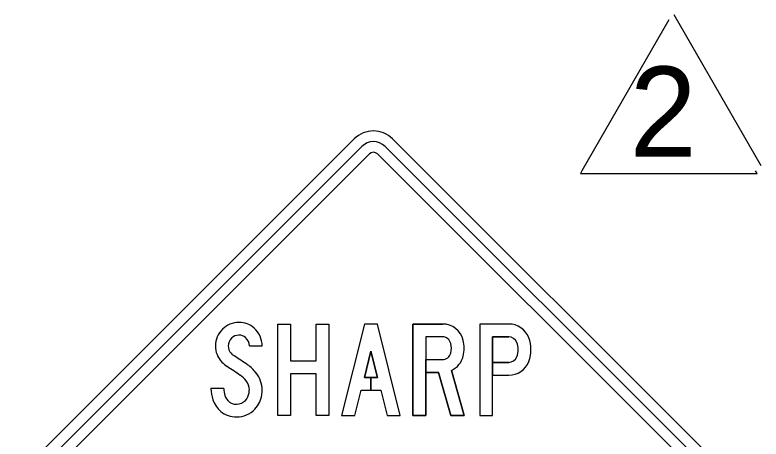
# Model space of a CAD drawing. Extents: x 2195 to 2411, y 202 to 481.
# Drawn here: x 2370.13 to 2382.1, y 351.9 to 358.71 of the extents above; entities that cross this region are included whole.
import ezdxf

# ---------------------------------------------------------------- set-up
doc = ezdxf.new("R2010")
doc.units = 0
for name, color, linetype in [('GSBWFILL', 7, 'Continuous'), ('GSCOLORFILL', 7, 'Continuous'), ('GSOUTLINE', 7, 'Continuous'), ('Level 1', 7, 'Continuous'), ('Level 60', 7, 'Continuous')]:
    doc.layers.add(name, color=color, linetype=linetype)

msp = doc.modelspace()

# ---------------------------------------------------------------- linework, layer by layer
at = {"layer": 'GSBWFILL'}
msp.add_line((2376.989, 353.176), (2376.989, 353.176), dxfattribs=at)
for points in [[(2374.345, 353.748), (2374.55, 353.748), (2374.55, 353.154), (2374.961, 353.154), (2374.961, 353.748), (2375.167, 353.748), (2375.167, 352.28), (2374.961, 352.28), (2374.961, 352.948), (2374.55, 352.948), (2374.55, 352.28), (2374.345, 352.28)], [(2375.842, 352.89), (2375.737, 352.89), (2375.842, 353.312), (2375.948, 352.89), (2375.842, 352.89), (2375.842, 352.684), (2375.999, 352.684), (2376.1, 352.28), (2376.312, 352.28), (2375.945, 353.748), (2375.739, 353.748), (2375.372, 352.28), (2375.584, 352.28), (2375.685, 352.684), (2375.842, 352.684)]]:
    msp.add_lwpolyline(points, close=True, dxfattribs=at)
for points in [[(2376.989, 353.543), (2376.723, 353.543), (2376.723, 352.28), (2376.517, 352.28), (2376.517, 353.748), (2376.989, 353.748)], [(2378.054, 353.748), (2377.589, 353.748), (2377.589, 352.28), (2377.794, 352.28), (2377.794, 353.543), (2378.054, 353.543)], [(2373.89, 353.395), (2374.095, 353.395)], [(2377.134, 353.002), (2377.339, 352.28), (2377.126, 352.28), (2376.929, 352.97), (2376.723, 352.97), (2376.723, 353.176), (2376.989, 353.176)], [(2378.054, 353.132), (2377.795, 353.132), (2377.795, 352.926), (2378.054, 352.926)], [(2373.479, 352.712), (2373.273, 352.712)]]:
    msp.add_lwpolyline(points, dxfattribs=at)
for centre, major_axis, start_param, end_param in [((2373.724, 353.396), (0, 0.378), 6.283184, 7.853982), ((2373.724, 353.409), (0, 0.365), 5.561989, 6.283185), ((2376.989, 353.403), (0, 0.345), 4.954755, 6.283185), ((2378.054, 353.403), (0, 0.345), 5.080657, 6.283185), ((2373.712, 353.395), (0, 0.384), 4.712389, 5.561989), ((2373.724, 353.396), (0, 0.173), 6.283183, 7.853981), ((2373.724, 353.409), (0, 0.16), 5.561989, 6.283185), ((2373.712, 353.395), (0, 0.178), 4.712389, 5.561989), ((2376.989, 353.403), (0, 0.139), 4.954755, 6.283185), ((2376.811, 353.359), (0, 0.528), 4.470023, 4.954755), ((2378.054, 353.403), (0, 0.139), 5.080657, 6.283185), ((2377.883, 353.337), (0, 0.528), 4.344121, 5.080657), ((2373.724, 353.396), (0, 0.379), 1.570796, 2.321595), ((2373.724, 353.396), (0, 0.173), 1.570796, 2.321595), ((2376.811, 353.359), (0, 0.323), 4.470023, 4.954755), ((2377.883, 353.337), (0, 0.323), 4.344121, 5.080657), ((2373.787, 353.454), (0, 0.259), 2.321595, 2.56746), ((2368.954, 345.982), (0, 8.64), 5.679143, 5.709053), ((2376.989, 353.315), (0, 0.139), 3.141593, 4.470023), ((2376.989, 353.315), (0, 0.345), 3.574819, 4.470023), ((2373.787, 353.454), (0, 0.464), 2.321595, 2.56746), ((2378.054, 353.271), (0, 0.139), 3.141593, 4.344121), ((2378.054, 353.271), (0, 0.345), 3.141593, 4.344121), ((2368.954, 345.982), (0, 8.434), 5.679143, 5.709053), ((2373.502, 352.573), (0, 0.632), 5.373599, 5.679143), ((2373.502, 352.573), (0, 0.427), 5.373599, 5.679143), ((2373.648, 352.687), (0, 0.447), 4.712389, 5.373599), ((2373.648, 352.687), (0, 0.242), 4.712389, 5.373599), ((2373.815, 352.712), (0, 0.541), 1.570808, 1.909921), ((2373.815, 352.712), (0, 0.336), 1.570816, 1.909918), ((2373.659, 352.678), (0, 0.23), 3.967076, 4.552917), ((2373.606, 352.687), (0, 0.283), 4.552917, 4.712389), ((2373.606, 352.687), (0, 0.489), 4.552917, 4.712389), ((2373.722, 352.68), (0, 0.443), 1.909925, 2.431476), ((2373.722, 352.68), (0, 0.238), 1.909925, 2.431476), ((2373.687, 352.652), (0, 0.192), 3.141593, 3.967076), ((2373.659, 352.678), (0, 0.436), 3.967076, 4.552917), ((2373.662, 352.61), (0, 0.145), 2.431476, 2.811358), ((2373.687, 352.684), (0, 0.224), 2.811358, 3.141593), ((2373.662, 352.61), (0, 0.351), 2.431476, 2.811358), ((2373.687, 352.684), (0, 0.429), 2.811358, 3.141593), ((2373.687, 352.652), (0, 0.397), 3.141593, 3.967076)]:
    msp.add_ellipse(centre, major_axis=major_axis, ratio=0.999997, start_param=start_param, end_param=end_param, dxfattribs=at)
at = {"layer": 'GSCOLORFILL'}
msp.add_line((2376.989, 353.176), (2376.989, 353.176), dxfattribs=at)
for points in [[(2374.345, 353.748), (2374.55, 353.748), (2374.55, 353.154), (2374.961, 353.154), (2374.961, 353.748), (2375.167, 353.748), (2375.167, 352.28), (2374.961, 352.28), (2374.961, 352.948), (2374.55, 352.948), (2374.55, 352.28), (2374.345, 352.28)], [(2375.842, 352.89), (2375.737, 352.89), (2375.842, 353.312), (2375.948, 352.89), (2375.842, 352.89), (2375.842, 352.684), (2375.999, 352.684), (2376.1, 352.28), (2376.312, 352.28), (2375.945, 353.748), (2375.739, 353.748), (2375.372, 352.28), (2375.584, 352.28), (2375.685, 352.684), (2375.842, 352.684)]]:
    msp.add_lwpolyline(points, close=True, dxfattribs=at)
for points in [[(2376.989, 353.543), (2376.723, 353.543), (2376.723, 352.28), (2376.517, 352.28), (2376.517, 353.748), (2376.989, 353.748)], [(2378.054, 353.748), (2377.589, 353.748), (2377.589, 352.28), (2377.794, 352.28), (2377.794, 353.543), (2378.054, 353.543)], [(2373.89, 353.395), (2374.095, 353.395)], [(2377.134, 353.002), (2377.339, 352.28), (2377.126, 352.28), (2376.929, 352.97), (2376.723, 352.97), (2376.723, 353.176), (2376.989, 353.176)], [(2378.054, 353.132), (2377.795, 353.132), (2377.795, 352.926), (2378.054, 352.926)], [(2373.479, 352.712), (2373.273, 352.712)]]:
    msp.add_lwpolyline(points, dxfattribs=at)
for centre, major_axis, start_param, end_param in [((2373.724, 353.396), (0, 0.378), 6.283184, 7.853982), ((2373.724, 353.409), (0, 0.365), 5.561989, 6.283185), ((2376.989, 353.403), (0, 0.345), 4.954755, 6.283185), ((2378.054, 353.403), (0, 0.345), 5.080657, 6.283185), ((2373.712, 353.395), (0, 0.384), 4.712389, 5.561989), ((2373.724, 353.396), (0, 0.173), 6.283183, 7.853981), ((2373.724, 353.409), (0, 0.16), 5.561989, 6.283185), ((2373.712, 353.395), (0, 0.178), 4.712389, 5.561989), ((2376.989, 353.403), (0, 0.139), 4.954755, 6.283185), ((2376.811, 353.359), (0, 0.528), 4.470023, 4.954755), ((2378.054, 353.403), (0, 0.139), 5.080657, 6.283185), ((2377.883, 353.337), (0, 0.528), 4.344121, 5.080657), ((2373.724, 353.396), (0, 0.379), 1.570796, 2.321595), ((2373.724, 353.396), (0, 0.173), 1.570796, 2.321595), ((2376.811, 353.359), (0, 0.323), 4.470023, 4.954755), ((2377.883, 353.337), (0, 0.323), 4.344121, 5.080657), ((2373.787, 353.454), (0, 0.259), 2.321595, 2.56746), ((2368.954, 345.982), (0, 8.64), 5.679143, 5.709053), ((2376.989, 353.315), (0, 0.139), 3.141593, 4.470023), ((2376.989, 353.315), (0, 0.345), 3.574819, 4.470023), ((2373.787, 353.454), (0, 0.464), 2.321595, 2.56746), ((2378.054, 353.271), (0, 0.139), 3.141593, 4.344121), ((2378.054, 353.271), (0, 0.345), 3.141593, 4.344121), ((2368.954, 345.982), (0, 8.434), 5.679143, 5.709053), ((2373.502, 352.573), (0, 0.632), 5.373599, 5.679143), ((2373.502, 352.573), (0, 0.427), 5.373599, 5.679143), ((2373.648, 352.687), (0, 0.447), 4.712389, 5.373599), ((2373.648, 352.687), (0, 0.242), 4.712389, 5.373599), ((2373.815, 352.712), (0, 0.541), 1.570808, 1.909921), ((2373.815, 352.712), (0, 0.336), 1.570816, 1.909918), ((2373.659, 352.678), (0, 0.23), 3.967076, 4.552917), ((2373.606, 352.687), (0, 0.283), 4.552917, 4.712389), ((2373.606, 352.687), (0, 0.489), 4.552917, 4.712389), ((2373.722, 352.68), (0, 0.443), 1.909925, 2.431476), ((2373.722, 352.68), (0, 0.238), 1.909925, 2.431476), ((2373.687, 352.652), (0, 0.192), 3.141593, 3.967076), ((2373.659, 352.678), (0, 0.436), 3.967076, 4.552917), ((2373.662, 352.61), (0, 0.145), 2.431476, 2.811358), ((2373.687, 352.684), (0, 0.224), 2.811358, 3.141593), ((2373.662, 352.61), (0, 0.351), 2.431476, 2.811358), ((2373.687, 352.684), (0, 0.429), 2.811358, 3.141593), ((2373.687, 352.652), (0, 0.397), 3.141593, 3.967076)]:
    msp.add_ellipse(centre, major_axis=major_axis, ratio=0.999997, start_param=start_param, end_param=end_param, dxfattribs=at)
at = {"layer": 'GSOUTLINE'}
for p, q in [((2376.989, 353.748), (2376.517, 353.748)), ((2378.054, 353.748), (2377.589, 353.748)), ((2376.989, 353.543), (2376.989, 353.543))]:
    msp.add_line(p, q, dxfattribs=at)
for points in [[(2374.345, 353.748), (2374.55, 353.748), (2374.55, 353.154), (2374.961, 353.154), (2374.961, 353.748), (2375.167, 353.748), (2375.167, 352.28), (2374.961, 352.28), (2374.961, 352.948), (2374.55, 352.948), (2374.55, 352.28), (2374.345, 352.28)], [(2375.685, 352.684), (2375.999, 352.684), (2376.1, 352.28), (2376.312, 352.28), (2375.945, 353.748), (2375.739, 353.748), (2375.372, 352.28), (2375.584, 352.28)], [(2375.948, 352.89), (2375.842, 353.312), (2375.737, 352.89)]]:
    msp.add_lwpolyline(points, close=True, dxfattribs=at)
for points in [[(2376.517, 353.748), (2376.517, 352.28), (2376.723, 352.28), (2376.723, 352.97), (2376.929, 352.97), (2377.126, 352.28), (2377.339, 352.28), (2377.134, 353.002)], [(2377.589, 353.748), (2377.589, 352.28), (2377.794, 352.28), (2377.794, 352.926), (2378.054, 352.926)], [(2376.989, 353.543), (2376.723, 353.543), (2376.723, 353.176), (2376.989, 353.176)], [(2378.054, 353.543), (2377.794, 353.543), (2377.794, 353.132), (2378.054, 353.132)], [(2373.89, 353.395), (2374.095, 353.395)], [(2373.479, 352.712), (2373.273, 352.712)]]:
    msp.add_lwpolyline(points, dxfattribs=at)
for centre, major_axis, start_param, end_param in [((2373.724, 353.396), (0, 0.378), 6.283184, 7.853982), ((2373.724, 353.409), (0, 0.365), 5.561989, 6.283185), ((2376.989, 353.403), (0, 0.345), 4.954755, 6.283185), ((2378.054, 353.403), (0, 0.345), 5.080657, 6.283185), ((2373.712, 353.395), (0, 0.384), 4.712389, 5.561989), ((2373.724, 353.396), (0, 0.173), 6.283183, 7.853981), ((2373.724, 353.409), (0, 0.16), 5.561989, 6.283185), ((2373.712, 353.395), (0, 0.178), 4.712389, 5.561989), ((2376.989, 353.403), (0, 0.139), 4.954755, 6.283185), ((2376.811, 353.359), (0, 0.528), 4.470023, 4.954755), ((2378.054, 353.403), (0, 0.139), 5.080657, 6.283185), ((2377.883, 353.337), (0, 0.528), 4.344121, 5.080657), ((2373.724, 353.396), (0, 0.379), 1.570796, 2.321595), ((2373.724, 353.396), (0, 0.173), 1.570796, 2.321595), ((2376.811, 353.359), (0, 0.323), 4.470023, 4.954755), ((2377.883, 353.337), (0, 0.323), 4.344121, 5.080657), ((2373.787, 353.454), (0, 0.259), 2.321595, 2.56746), ((2368.954, 345.982), (0, 8.64), 5.679143, 5.709053), ((2376.989, 353.315), (0, 0.139), 3.141593, 4.470023), ((2376.989, 353.315), (0, 0.345), 3.574819, 4.470023), ((2373.787, 353.454), (0, 0.464), 2.321595, 2.56746), ((2378.054, 353.271), (0, 0.139), 3.141593, 4.344121), ((2378.054, 353.271), (0, 0.345), 3.141593, 4.344121), ((2368.954, 345.982), (0, 8.434), 5.679143, 5.709053), ((2373.502, 352.573), (0, 0.632), 5.373599, 5.679143), ((2373.502, 352.573), (0, 0.427), 5.373599, 5.679143), ((2373.648, 352.687), (0, 0.447), 4.712389, 5.373599), ((2373.648, 352.687), (0, 0.242), 4.712389, 5.373599), ((2373.815, 352.712), (0, 0.541), 1.570808, 1.909921), ((2373.815, 352.712), (0, 0.336), 1.570816, 1.909918), ((2373.659, 352.678), (0, 0.23), 3.967076, 4.552917), ((2373.606, 352.687), (0, 0.283), 4.552917, 4.712389), ((2373.606, 352.687), (0, 0.489), 4.552917, 4.712389), ((2373.722, 352.68), (0, 0.443), 1.909925, 2.431476), ((2373.722, 352.68), (0, 0.238), 1.909925, 2.431476), ((2373.687, 352.652), (0, 0.192), 3.141593, 3.967076), ((2373.659, 352.678), (0, 0.436), 3.967076, 4.552917), ((2373.662, 352.61), (0, 0.145), 2.431476, 2.811358), ((2373.687, 352.684), (0, 0.224), 2.811358, 3.141593), ((2373.662, 352.61), (0, 0.351), 2.431476, 2.811358), ((2373.687, 352.684), (0, 0.429), 2.811358, 3.141593), ((2373.687, 352.652), (0, 0.397), 3.141593, 3.967076)]:
    msp.add_ellipse(centre, major_axis=major_axis, ratio=0.999997, start_param=start_param, end_param=end_param, dxfattribs=at)
at = {"layer": 'Level 1'}
for p, q in [((2370.127, 351.275), (2375.574, 356.721)), ((2376.19, 356.722), (2381.64, 351.278)), ((2370.249, 351.153), (2375.695, 356.6)), ((2376.069, 356.6), (2381.519, 351.157)), ((2370.37, 351.032), (2375.817, 356.479)), ((2375.948, 356.479), (2381.398, 351.035))]:
    msp.add_line(p, q, dxfattribs=at)
for radius in [0.436, 0.264, 0.0926]:
    msp.add_arc((2375.882, 356.413), radius, 45.0349, 135, dxfattribs=at)
at = {"layer": 'Level 60'}
for points in [[(2380.623, 358.635), (2379.23, 356.21)], [(2382.105, 356.287), (2380.711, 358.712)], [(2379.23, 356.21), (2379.204, 356.165), (2382.043, 356.165), (2382.017, 356.21)]]:
    msp.add_lwpolyline(points, dxfattribs=at)

# ---------------------------------------------------------------- texts
msp.add_text('2', height=1.448, rotation=360, dxfattribs=at).set_placement((2379.996, 356.434))

doc.saveas('drawing.dxf')
